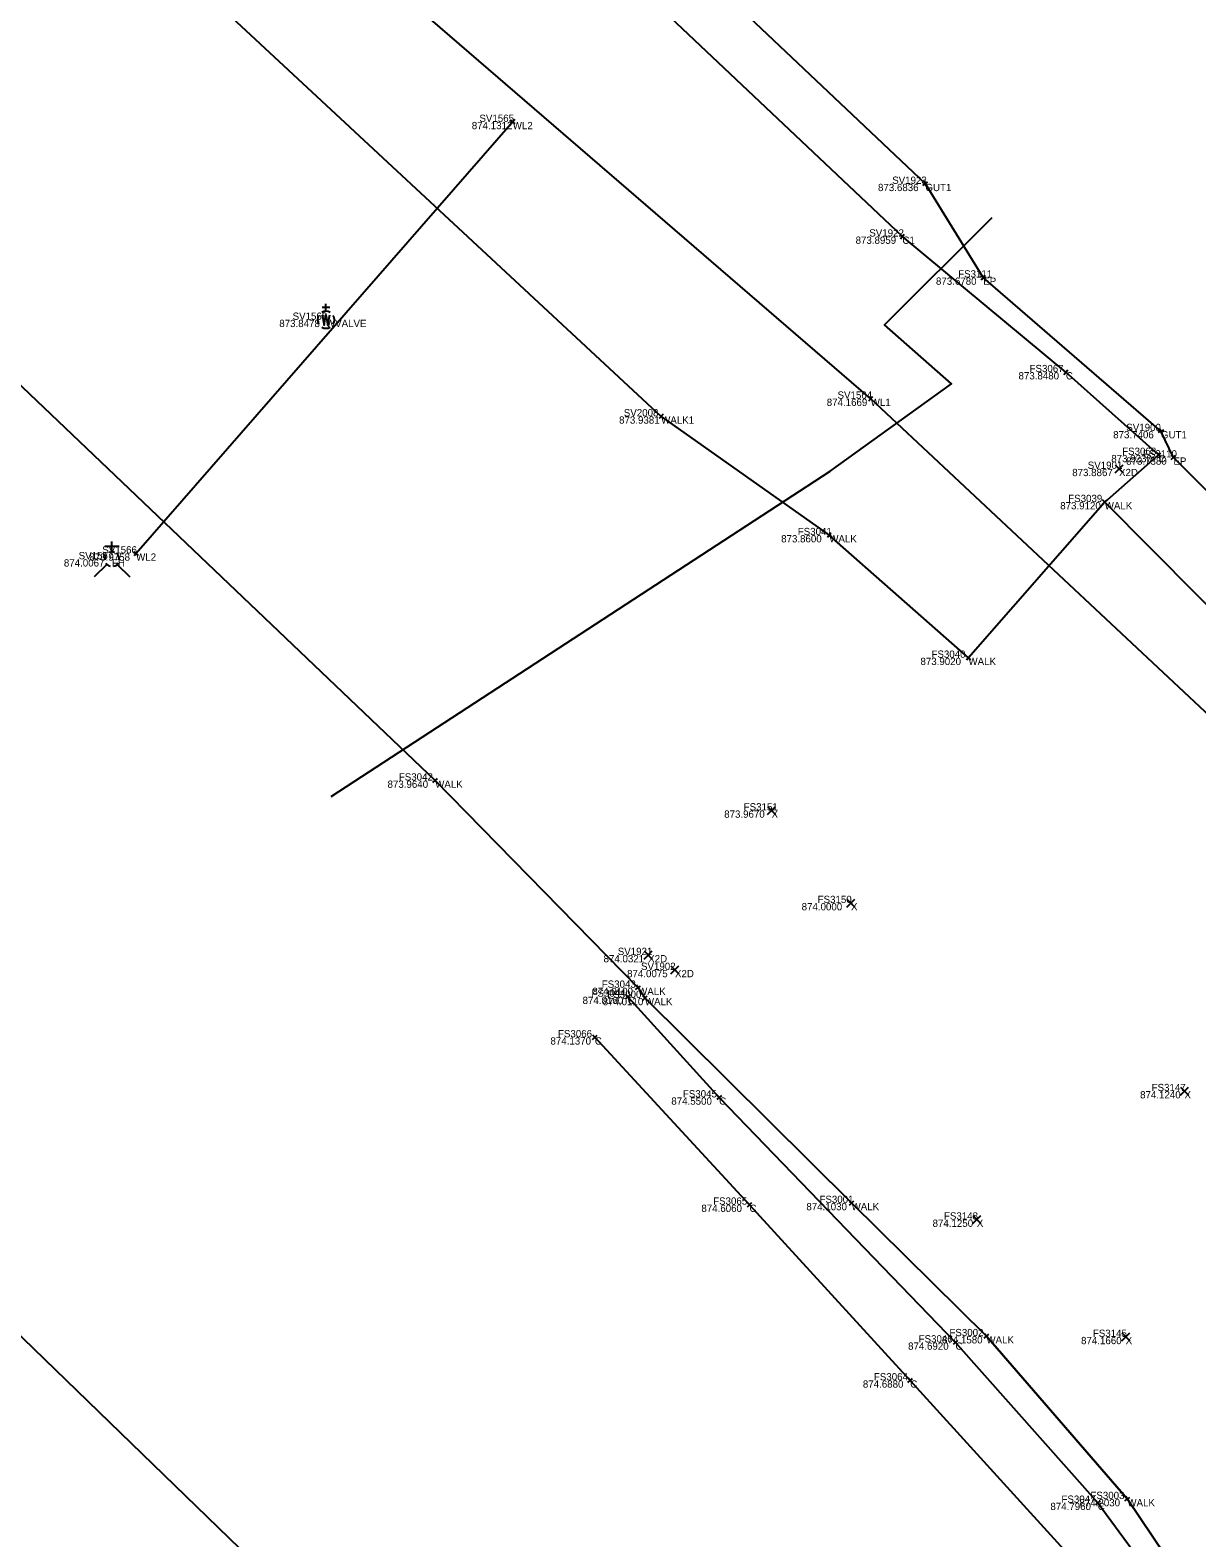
# Model space of a CAD drawing. Extents: x 1479481 to 1575806, y 316056 to 379927.
# Drawn here: x 1480127.81 to 1480137.43, y 379421.16 to 379433.6 of the extents above; entities that cross this region are included whole.
import ezdxf

# ---------------------------------------------------------------- set-up
doc = ezdxf.new("R2010")
doc.units = 0
for name, color, linetype in [('PM_X_Crosswalk', 7, 'Continuous'), ('PV_X_Curb', 7, 'Continuous'), ('PV_X_Walk', 7, 'Continuous'), ('SV_X_Break_Lines', 7, 'Continuous'), ('SV_X_Random_Point', 7, 'Continuous'), ('SV_X_Shot_Marker', 7, 'Continuous'), ('SV_X_Text_Comment', 7, 'Continuous'), ('SV_X_Text_Elevation', 7, 'Continuous'), ('SV_X_Text_Name', 7, 'Continuous'), ('UT_X_Water', 7, 'Continuous'), ('UT_X_Water_Cells', 7, 'Continuous')]:
    doc.layers.add(name, color=color, linetype=linetype)

msp = doc.modelspace()

# ---------------------------------------------------------------- linework, layer by layer
at = {"layer": 'PM_X_Crosswalk'}
msp.add_lwpolyline([(1480130.288, 379427.276), (1480134.405, 379429.96), (1480135.405, 379430.682), (1480134.853, 379431.169), (1480135.74, 379432.055)], dxfattribs=at)
at = {"layer": 'PV_X_Curb'}
for points in [[(1480144.119, 379408.692), (1480144.24, 379410.484), (1480144.247, 379412.184), (1480144.276, 379413.727), (1480144.183, 379415.462), (1480143.996, 379417.344), (1480143.813, 379419.16), (1480143.496, 379420.71), (1480143.015, 379422.278), (1480142.354, 379423.817), (1480141.636, 379425.054), (1480140.711, 379426.236), (1480139.646, 379427.551), (1480138.485, 379428.822), (1480137.236, 379430.074), (1480137.133, 379430.292), (1480135.667, 379431.559), (1480135.19, 379432.332), (1480118.45, 379448.16)], [(1480143.467, 379408.427), (1480143.491, 379410.102), (1480143.626, 379411.891), (1480143.667, 379412.715), (1480143.643, 379414.145), (1480143.592, 379415.709), (1480143.406, 379417.136), (1480143.175, 379418.964), (1480142.832, 379420.583), (1480142.491, 379421.692), (1480141.812, 379423.272), (1480140.724, 379425.16), (1480139.421, 379426.804), (1480138.202, 379428.161), (1480136.669, 379429.706), (1480137.114, 379430.095), (1480136.349, 379430.778), (1480135, 379431.897), (1480118.039, 379447.914)], [(1480132.735, 379425.624), (1480133.489, 379424.793), (1480135.438, 379422.771), (1480136.612, 379421.448), (1480137.609, 379420.095), (1480138.484, 379418.724), (1480139.167, 379417.086), (1480139.644, 379414.697), (1480139.873, 379412.175), (1480139.928, 379410.1), (1480139.896, 379409.023), (1480139.487, 379409.126), (1480139.398, 379410.762), (1480139.445, 379412.342), (1480139.28, 379413.822), (1480139.072, 379415.451), (1480138.646, 379416.869), (1480138.065, 379418.417), (1480137.434, 379419.594), (1480136.416, 379420.968), (1480135.065, 379422.458), (1480133.739, 379423.908), (1480132.463, 379425.289)]]:
    msp.add_lwpolyline(points, dxfattribs=at)
at = {"layer": 'PV_X_Walk'}
for points in [[(1480106.316, 379456.227), (1480120.51, 379442.034), (1480133.01, 379430.413), (1480134.397, 379429.433)], [(1480121.511, 379381.77), (1480134.604, 379395.58), (1480136.695, 379398.148), (1480138.804, 379401.064), (1480139.196, 379402.304), (1480139.794, 379404.164), (1480140.245, 379405.64), (1480140.457, 379406.671), (1480140.54, 379407.685), (1480140.684, 379408.982), (1480140.078, 379409.022), (1480140.106, 379411.022), (1480140.05, 379412.608), (1480139.852, 379414.468), (1480139.524, 379416.334), (1480139.163, 379417.424), (1480138.324, 379419.293), (1480136.856, 379421.479), (1480135.693, 379422.823), (1480134.581, 379423.922), (1480132.876, 379425.614), (1480132.82, 379425.698), (1480131.146, 379427.408), (1480114.834, 379442.96)], [(1480143.467, 379408.427), (1480143.491, 379410.102), (1480143.626, 379411.891), (1480143.667, 379412.715), (1480143.643, 379414.145), (1480143.592, 379415.709), (1480143.406, 379417.136), (1480143.175, 379418.964), (1480142.832, 379420.583), (1480142.491, 379421.692), (1480141.812, 379423.272), (1480140.724, 379425.16), (1480139.421, 379426.804), (1480138.202, 379428.161), (1480136.669, 379429.706), (1480135.545, 379428.421), (1480134.397, 379429.433)], [(1480132.876, 379425.614), (1480134.581, 379423.922), (1480135.693, 379422.823), (1480136.856, 379421.479), (1480138.324, 379419.293), (1480139.163, 379417.424), (1480139.524, 379416.334), (1480139.852, 379414.468), (1480140.05, 379412.608), (1480140.106, 379411.022), (1480140.078, 379409.022), (1480140.684, 379408.982), (1480140.54, 379407.685)]]:
    msp.add_lwpolyline(points, dxfattribs=at)
at = {"layer": 'SV_X_Break_Lines'}
msp.add_lwpolyline([(1480127.721, 379395.358), (1480131.799, 379398.039), (1480133.273, 379401.352), (1480135.459, 379407.36), (1480135.6, 379409.555), (1480135.793, 379413.076), (1480135.014, 379415.657), (1480133.026, 379417.684), (1480123.803, 379426.624), (1480113.121, 379435.343), (1480106.984, 379440.926), (1480103.73, 379443.918), (1480102.529, 379445.074), (1480100.774, 379445.951), (1480096.595, 379444.059), (1480092.174, 379441.029), (1480086.377, 379436.591)], dxfattribs=at)
at = {"layer": 'SV_X_Random_Point'}
for p, q in [((1480136.754, 379429.946), (1480136.82, 379430.013)), ((1480136.754, 379430.013), (1480136.82, 379429.946)), ((1480133.888, 379427.128), (1480133.954, 379427.194)), ((1480133.888, 379427.194), (1480133.954, 379427.128)), ((1480134.543, 379426.364), (1480134.609, 379426.43)), ((1480134.543, 379426.43), (1480134.609, 379426.364)), ((1480132.87, 379425.935), (1480132.936, 379426.002)), ((1480132.87, 379426.002), (1480132.936, 379425.935)), ((1480133.091, 379425.812), (1480133.157, 379425.879)), ((1480133.091, 379425.879), (1480133.157, 379425.812)), ((1480137.294, 379424.812), (1480137.36, 379424.878)), ((1480137.294, 379424.878), (1480137.36, 379424.812)), ((1480135.581, 379423.752), (1480135.647, 379423.818)), ((1480135.581, 379423.818), (1480135.647, 379423.752)), ((1480136.809, 379422.784), (1480136.875, 379422.85)), ((1480136.809, 379422.85), (1480136.875, 379422.784))]:
    msp.add_line(p, q, dxfattribs=at)
at = {"layer": 'SV_X_Shot_Marker'}
for p, q in [((1480131.805, 379432.827), (1480131.767, 379432.86)), ((1480131.802, 379432.862), (1480131.77, 379432.825)), ((1480131.786, 379432.843), (1480131.786, 379432.843)), ((1480135.169, 379432.319), (1480135.211, 379432.345)), ((1480135.203, 379432.311), (1480135.177, 379432.353)), ((1480135.19, 379432.332), (1480135.19, 379432.332)), ((1480135.019, 379431.881), (1480134.981, 379431.913)), ((1480134.984, 379431.878), (1480135.016, 379431.916)), ((1480135, 379431.897), (1480135, 379431.897)), ((1480135.686, 379431.543), (1480135.648, 379431.575)), ((1480135.651, 379431.54), (1480135.683, 379431.578)), ((1480135.667, 379431.559), (1480135.667, 379431.559)), ((1480136.368, 379430.761), (1480136.33, 379430.795)), ((1480136.332, 379430.759), (1480136.366, 379430.797)), ((1480136.349, 379430.778), (1480136.349, 379430.778)), ((1480134.757, 379430.542), (1480134.721, 379430.576)), ((1480134.722, 379430.541), (1480134.756, 379430.578)), ((1480134.739, 379430.559), (1480134.739, 379430.559)), ((1480132.992, 379430.43), (1480133.028, 379430.396)), ((1480133.027, 379430.432), (1480132.993, 379430.395)), ((1480133.01, 379430.413), (1480133.01, 379430.413)), ((1480137.11, 379430.282), (1480137.156, 379430.303)), ((1480137.144, 379430.27), (1480137.122, 379430.315)), ((1480137.133, 379430.292), (1480137.133, 379430.292)), ((1480137.095, 379430.079), (1480137.133, 379430.112)), ((1480137.098, 379430.114), (1480137.131, 379430.077)), ((1480137.114, 379430.095), (1480137.114, 379430.095)), ((1480137.218, 379430.056), (1480137.254, 379430.092)), ((1480137.254, 379430.056), (1480137.218, 379430.092)), ((1480137.236, 379430.074), (1480137.236, 379430.074)), ((1480136.651, 379429.688), (1480136.687, 379429.724)), ((1480136.687, 379429.688), (1480136.651, 379429.724)), ((1480136.669, 379429.706), (1480136.669, 379429.706)), ((1480134.377, 379429.447), (1480134.417, 379429.419)), ((1480134.411, 379429.453), (1480134.383, 379429.413)), ((1480134.397, 379429.433), (1480134.397, 379429.433)), ((1480128.698, 379429.265), (1480128.66, 379429.298)), ((1480128.695, 379429.301), (1480128.663, 379429.263)), ((1480128.679, 379429.282), (1480128.679, 379429.282)), ((1480135.564, 379428.405), (1480135.526, 379428.437)), ((1480135.561, 379428.44), (1480135.529, 379428.402)), ((1480135.545, 379428.421), (1480135.545, 379428.421)), ((1480131.128, 379427.391), (1480131.164, 379427.425)), ((1480131.163, 379427.39), (1480131.129, 379427.426)), ((1480131.146, 379427.408), (1480131.146, 379427.408)), ((1480132.754, 379425.641), (1480132.716, 379425.607)), ((1480132.718, 379425.643), (1480132.752, 379425.605)), ((1480132.735, 379425.624), (1480132.735, 379425.624)), ((1480132.799, 379425.684), (1480132.841, 379425.712)), ((1480132.834, 379425.677), (1480132.806, 379425.719)), ((1480132.82, 379425.698), (1480132.82, 379425.698)), ((1480132.858, 379425.596), (1480132.894, 379425.632)), ((1480132.894, 379425.596), (1480132.858, 379425.632)), ((1480132.876, 379425.614), (1480132.876, 379425.614)), ((1480132.445, 379425.272), (1480132.481, 379425.306)), ((1480132.48, 379425.271), (1480132.446, 379425.307)), ((1480132.463, 379425.289), (1480132.463, 379425.289)), ((1480133.508, 379424.81), (1480133.47, 379424.776)), ((1480133.472, 379424.812), (1480133.506, 379424.774)), ((1480133.489, 379424.793), (1480133.489, 379424.793)), ((1480133.721, 379423.891), (1480133.757, 379423.925)), ((1480133.756, 379423.89), (1480133.722, 379423.926)), ((1480133.739, 379423.908), (1480133.739, 379423.908)), ((1480134.563, 379423.904), (1480134.599, 379423.94)), ((1480134.599, 379423.904), (1480134.563, 379423.94)), ((1480134.581, 379423.922), (1480134.581, 379423.922)), ((1480135.456, 379422.788), (1480135.42, 379422.754)), ((1480135.421, 379422.789), (1480135.455, 379422.753)), ((1480135.438, 379422.771), (1480135.438, 379422.771)), ((1480135.674, 379422.807), (1480135.712, 379422.839)), ((1480135.709, 379422.804), (1480135.677, 379422.842)), ((1480135.693, 379422.823), (1480135.693, 379422.823)), ((1480135.046, 379422.441), (1480135.084, 379422.475)), ((1480135.082, 379422.439), (1480135.048, 379422.477)), ((1480135.065, 379422.458), (1480135.065, 379422.458)), ((1480136.835, 379421.465), (1480136.877, 379421.493)), ((1480136.87, 379421.458), (1480136.842, 379421.5)), ((1480136.631, 379421.465), (1480136.593, 379421.431)), ((1480136.595, 379421.467), (1480136.629, 379421.429)), ((1480136.612, 379421.448), (1480136.612, 379421.448)), ((1480136.856, 379421.479), (1480136.856, 379421.479))]:
    msp.add_line(p, q, dxfattribs=at)
at = {"layer": 'UT_X_Water'}
for points in [[(1480234.677, 379335.863), (1480225.088, 379345.601), (1480208.322, 379361.342), (1480207.346, 379362.25), (1480199.528, 379369.768), (1480193.21, 379375.651), (1480182.823, 379385.139), (1480177.927, 379389.525), (1480169.423, 379398.321), (1480161.035, 379406.189), (1480144.924, 379421.019), (1480134.739, 379430.559), (1480121.485, 379441.998), (1480113.085, 379450.369), (1480106.418, 379456.915), (1480094.539, 379467.985), (1480089.15, 379472.551), (1480086.751, 379474.713), (1480073.459, 379487.337), (1480068.123, 379493.187), (1480050.678, 379510.207), (1480044.404, 379515.873)], [(1480131.786, 379432.843), (1480128.679, 379429.282)]]:
    msp.add_lwpolyline(points, dxfattribs=at)
at = {"layer": 'UT_X_Water_Cells'}
for p, q in [((1480130.245, 379431.28), (1480130.245, 379431.343)), ((1480130.277, 379431.312), (1480130.213, 379431.312)), ((1480130.245, 379431.21), (1480130.245, 379431.21)), ((1480128.54, 379429.338), (1480128.42, 379429.338)), ((1480128.48, 379429.295), (1480128.48, 379429.381)), ((1480128.48, 379429.234), (1480128.48, 379429.234)), ((1480128.48, 379429.234), (1480128.48, 379429.234)), ((1480128.438, 379429.192), (1480128.334, 379429.088)), ((1480128.522, 379429.192), (1480128.626, 379429.088))]:
    msp.add_line(p, q, dxfattribs=at)
msp.add_lwpolyline([(1480130.213, 379431.251), (1480130.229, 379431.165), (1480130.245, 379431.251), (1480130.261, 379431.165), (1480130.277, 379431.251)], dxfattribs=at)
for centre, radius, start, end in [((1480130.245, 379431.21), 0.07, 150.0184, 209.9816), ((1480130.245, 379431.21), 0.07, 60.0184, 120.0157), ((1480130.245, 379431.21), 0.07, 330.0184, 29.9816), ((1480130.245, 379431.21), 0.07, 239.9843, 299.9816), ((1480128.48, 379429.234), 0.06, 140.021, 184.0629), ((1480128.48, 379429.234), 0.06, 68.1395, 112.038), ((1480128.48, 379429.234), 0.06, 356.0165, 39.9889), ((1480128.48, 379429.234), 0.06, 211.8788, 255.8479), ((1480128.48, 379429.234), 0.06, 283.8239, 329.9097)]:
    msp.add_arc(centre, radius, start, end, dxfattribs=at)

# ---------------------------------------------------------------- texts
at = {"layer": 'SV_X_Text_Comment'}
for s, p in [('WL2', (1480131.786, 379432.783)), ('GUT1', (1480135.19, 379432.272)), ('C1', (1480135, 379431.837)), ('EP', (1480135.667, 379431.499)), ('WVALVE', (1480130.245, 379431.15)), ('C', (1480136.349, 379430.718)), ('WL1', (1480134.739, 379430.499)), ('WALK1', (1480133.01, 379430.353)), ('GUT1', (1480137.133, 379430.232)), ('C', (1480137.114, 379430.035)), ('X2D', (1480136.787, 379429.92)), ('EP', (1480137.236, 379430.014)), ('WALK', (1480136.669, 379429.646)), ('WALK', (1480134.397, 379429.373)), ('FH', (1480128.48, 379429.174)), ('WL2', (1480128.679, 379429.222)), ('WALK', (1480135.545, 379428.361)), ('WALK', (1480131.146, 379427.348)), ('X', (1480133.921, 379427.101)), ('X', (1480134.576, 379426.337)), ('X2D', (1480132.903, 379425.908)), ('X2D', (1480133.124, 379425.785)), ('C', (1480132.735, 379425.564)), ('WALK', (1480132.82, 379425.638)), ('WALK', (1480132.876, 379425.554)), ('C', (1480132.463, 379425.229)), ('C', (1480133.489, 379424.733)), ('X', (1480137.327, 379424.785)), ('C', (1480133.739, 379423.848)), ('WALK', (1480134.581, 379423.862)), ('X', (1480135.614, 379423.725)), ('C', (1480135.438, 379422.711)), ('WALK', (1480135.693, 379422.763)), ('X', (1480136.842, 379422.757)), ('C', (1480135.065, 379422.398)), ('C', (1480136.612, 379421.388)), ('WALK', (1480136.856, 379421.419))]:
    msp.add_text(s, height=0.06, dxfattribs=at).set_placement(p)
at = {"layer": 'SV_X_Text_Elevation'}
for s, p in [('874.1312', (1480131.448, 379432.783)), ('873.6836', (1480134.799, 379432.272)), ('873.8959', (1480134.614, 379431.837)), ('873.6780', (1480135.277, 379431.499)), ('873.8478', (1480129.86, 379431.15)), ('873.8480', (1480135.958, 379430.718)), ('874.1669', (1480134.376, 379430.499)), ('873.9381', (1480132.663, 379430.353)), ('873.7406', (1480136.739, 379430.232)), ('873.9230', (1480136.723, 379430.035)), ('873.8867', (1480136.401, 379429.92)), ('873.7380', (1480136.846, 379430.014)), ('873.9120', (1480136.302, 379429.646)), ('873.8600', (1480134, 379429.373)), ('874.0067', (1480128.083, 379429.174)), ('873.9758', (1480128.294, 379429.222)), ('873.9020', (1480135.149, 379428.361)), ('873.9640', (1480130.753, 379427.348)), ('873.9670', (1480133.53, 379427.101)), ('874.0000', (1480134.169, 379426.337)), ('874.0321', (1480132.535, 379425.908)), ('874.0075', (1480132.729, 379425.785)), ('874.0160', (1480132.362, 379425.564)), ('874.0100', (1480132.443, 379425.638)), ('874.0110', (1480132.528, 379425.554)), ('874.1370', (1480132.097, 379425.229)), ('874.5500', (1480133.094, 379424.733)), ('874.1240', (1480136.961, 379424.785)), ('874.6060', (1480133.342, 379423.848)), ('874.1030', (1480134.208, 379423.862)), ('874.1250', (1480135.249, 379423.725)), ('874.6920', (1480135.047, 379422.711)), ('874.1580', (1480135.327, 379422.763)), ('874.1660', (1480136.474, 379422.757)), ('874.6880', (1480134.674, 379422.398)), ('874.7960', (1480136.221, 379421.388)), ('874.2030', (1480136.461, 379421.419))]:
    msp.add_text(s, height=0.06, dxfattribs=at).set_placement(p)
at = {"layer": 'SV_X_Text_Name'}
for s, p in [('SV1565', (1480131.511, 379432.843)), ('SV1923', (1480134.916, 379432.332)), ('SV1922', (1480134.727, 379431.897)), ('FS3111', (1480135.46, 379431.559)), ('SV1568', (1480129.97, 379431.21)), ('FS3067', (1480136.049, 379430.778)), ('SV1564', (1480134.465, 379430.559)), ('SV2008', (1480132.702, 379430.413)), ('SV1900', (1480136.847, 379430.292)), ('FS3068', (1480136.813, 379430.095)), ('FS3110', (1480136.984, 379430.074)), ('SV1901', (1480136.529, 379429.98)), ('FS3039', (1480136.368, 379429.706)), ('FS3041', (1480134.137, 379429.433)), ('SV1566', (1480128.4, 379429.282)), ('SV1567', (1480128.205, 379429.234)), ('FS3040', (1480135.24, 379428.421)), ('FS3042', (1480130.846, 379427.408)), ('FS3151', (1480133.691, 379427.161)), ('FS3150', (1480134.301, 379426.397)), ('SV1921', (1480132.652, 379425.968)), ('SV1902', (1480132.844, 379425.845)), ('FS3043', (1480132.52, 379425.698)), ('FS3044', (1480132.435, 379425.624)), ('FS3000', (1480132.566, 379425.614)), ('FS3066', (1480132.159, 379425.289)), ('FS3045', (1480133.189, 379424.793)), ('FS3147', (1480137.056, 379424.845)), ('FS3001', (1480134.316, 379423.922)), ('FS3065', (1480133.439, 379423.908)), ('FS3148', (1480135.343, 379423.785)), ('FS3002', (1480135.388, 379422.823)), ('FS3145', (1480136.571, 379422.817)), ('FS3046', (1480135.134, 379422.771)), ('FS3064', (1480134.765, 379422.458)), ('FS3047', (1480136.312, 379421.448)), ('FS3003', (1480136.551, 379421.479))]:
    msp.add_text(s, height=0.06, dxfattribs=at).set_placement(p)

doc.saveas('drawing.dxf')
